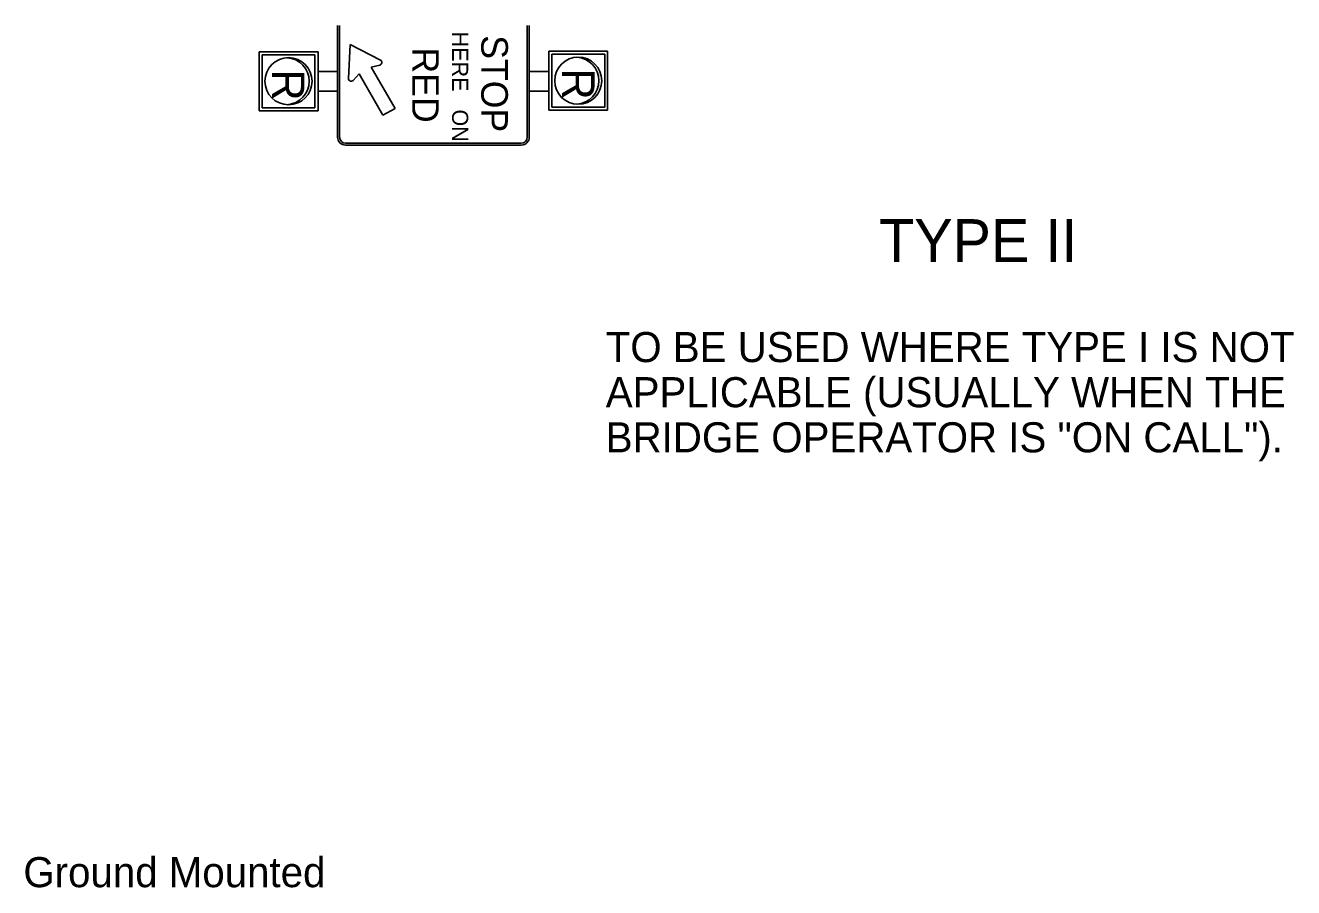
# Model space of a CAD drawing. Extents: x 10000 to 10825, y 10000 to 10530.
# Drawn here: x 10485.6 to 10633.1, y 10282.4 to 10382.7 of the extents above; entities that cross this region are included whole.
import ezdxf

# ---------------------------------------------------------------- set-up
doc = ezdxf.new("R2010")
doc.units = 0
doc.layers.add('Default', color=7, linetype='Continuous')
doc.layers.add('TextStructures', color=7, linetype='Continuous')

msp = doc.modelspace()

# ---------------------------------------------------------------- linework, layer by layer
at = {"layer": 'Default'}
for p, q in [((10521.94, 10382.75), (10521.94, 10369.74)), ((10522.17, 10382.75), (10522.17, 10369.74)), ((10544, 10369.74), (10544, 10382.75)), ((10544.23, 10369.74), (10544.23, 10382.75)), ((10512.81, 10379.68), (10512.81, 10372.82)), ((10519.66, 10379.68), (10512.81, 10379.68)), ((10513.15, 10379.33), (10513.15, 10373.17)), ((10519.31, 10379.33), (10513.15, 10379.33)), ((10519.31, 10373.17), (10519.31, 10379.33)), ((10519.66, 10372.82), (10519.66, 10379.68)), ((10523.39, 10380.53), (10523.21, 10376.57)), ((10526.91, 10378.7), (10523.39, 10380.53)), ((10546.49, 10379.74), (10546.49, 10372.89)), ((10553.34, 10379.74), (10546.49, 10379.74)), ((10546.84, 10379.4), (10546.84, 10373.23)), ((10553, 10379.4), (10546.84, 10379.4)), ((10553, 10373.23), (10553, 10379.4)), ((10553.34, 10372.89), (10553.34, 10379.74)), ((10525.84, 10377.9), (10526.83, 10378.13)), ((10528.62, 10373.09), (10525.84, 10377.9)), ((10519.67, 10377.38), (10521.94, 10377.38)), ((10523.73, 10376.34), (10524.43, 10377.09)), ((10524.43, 10377.09), (10527.21, 10372.28)), ((10544.23, 10377.38), (10546.49, 10377.38)), ((10519.67, 10375.11), (10521.94, 10375.11)), ((10544.23, 10375.11), (10546.49, 10375.11)), ((10512.81, 10372.82), (10519.66, 10372.82)), ((10513.15, 10373.17), (10519.31, 10373.17)), ((10527.21, 10372.28), (10528.62, 10373.09)), ((10546.49, 10372.89), (10553.34, 10372.89)), ((10546.84, 10373.23), (10553, 10373.23)), ((10522.87, 10369.05), (10543.3, 10369.05)), ((10522.87, 10368.82), (10543.3, 10368.82))]:
    msp.add_line(p, q, dxfattribs=at)
for centre, radius, start, end in [((10515.89, 10376.25), 2.74, 273.5833, 86.4167), ((10526.77, 10378.43), 0.305, 283.0563, 62.5967), ((10549.58, 10376.31), 2.74, 273.5833, 86.4167), ((10523.51, 10376.55), 0.305, 177.4033, 316.9437), ((10522.87, 10369.74), 0.929, 180, 270), ((10522.87, 10369.74), 0.697, 180, 270), ((10543.3, 10369.74), 0.929, 270, 360), ((10543.3, 10369.74), 0.697, 270, 360)]:
    msp.add_arc(centre, radius, start, end, dxfattribs=at)
at = {"layer": 'TextStructures'}
for centre in [(10516.23, 10376.25), (10549.92, 10376.31)]:
    msp.add_circle(centre, 2.74, dxfattribs=at)

# ---------------------------------------------------------------- texts
at = {"layer": 'Default'}
for s, height, p in [('HERE   ON', 1.873, (10535.25, 10382.01)), ('STOP', 3.098, (10538.64, 10381.6)), ('RED', 3.098, (10530.61, 10380.17))]:
    msp.add_text(s, height=height, rotation=270, dxfattribs=at).set_placement(p)
at = {"layer": 'TextStructures'}
for s, height, rotation, p in [('R', 3.78, 270, (10514.3, 10377.63)), ('R', 3.78, 270, (10548.04, 10377.74)), ('TYPE II ', 5, 0.0007, (10584.91, 10355.2)), ('TO BE USED WHERE TYPE I IS NOT ', 3.5, 0.0007, (10553.12, 10343.57)), ('APPLICABLE (USUALLY WHEN THE ', 3.5, 0.0007, (10553.12, 10338.32)), ('BRIDGE OPERATOR IS "ON CALL").', 3.5, 0.0007, (10553.12, 10333.07)), ('Ground Mounted', 3.5, 0.0007, (10485.4, 10282.48))]:
    msp.add_text(s, height=height, rotation=rotation, dxfattribs=at).set_placement(p)

doc.saveas('drawing.dxf')
